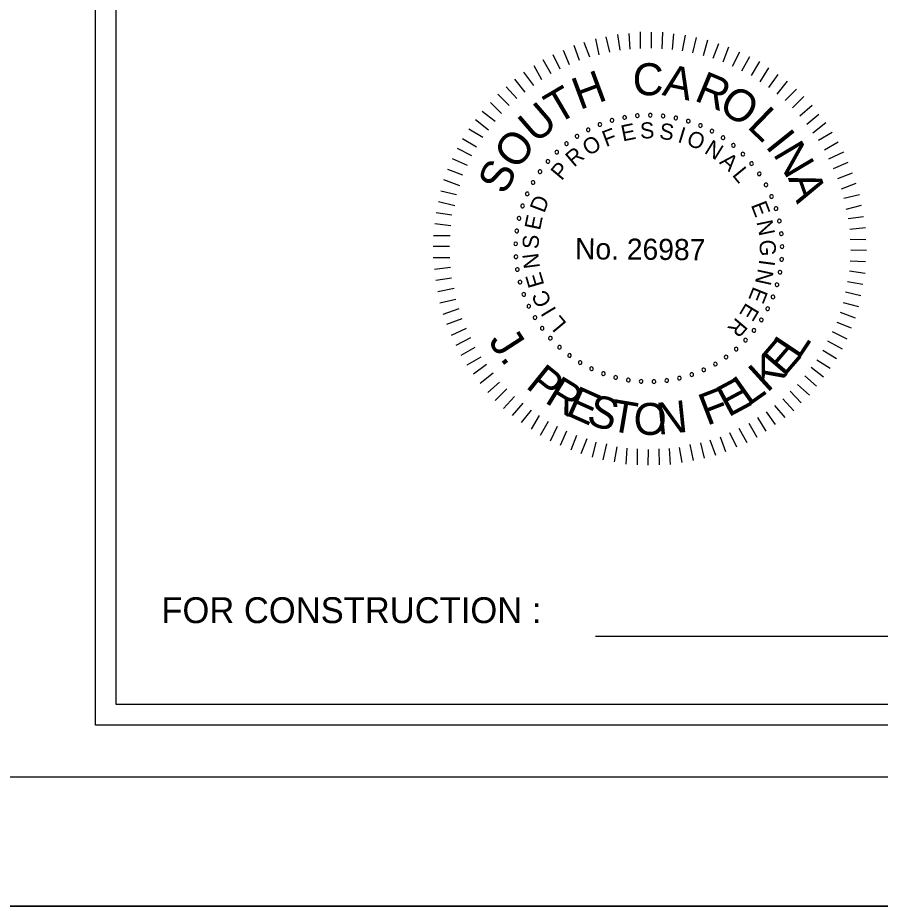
# Model space of a CAD drawing. Extents: x -1142 to 658, y -589 to 511.
# Drawn here: x 260.1 to 427, y -589.3 to -417.4 of the extents above; entities that cross this region are included whole.
import ezdxf

# ---------------------------------------------------------------- set-up
doc = ezdxf.new("R2010")
doc.units = 0
for name, color, linetype in [('BR_BORDER LINES', 7, 'Continuous'), ('BR_TEXT', 7, 'Continuous'), ('Default', 7, 'Continuous'), ('Level 31', 7, 'Continuous'), ('RD_SHT_IplotShp', 7, 'Continuous')]:
    doc.layers.add(name, color=color, linetype=linetype)

msp = doc.modelspace()

# ---------------------------------------------------------------- linework, layer by layer
at = {"layer": 'BR_BORDER LINES'}
msp.add_line((-1041.79, -564.26), (633.21, -564.26), dxfattribs=at)
at = {"layer": 'BR_TEXT'}
for p, q in [((374.63, -424.04), (373.93, -421.08)), ((376.61, -423.67), (376.16, -420.62)), ((378.58, -423.47), (378.4, -420.43)), ((380.56, -423.36), (380.59, -420.14)), ((382.66, -423.25), (382.69, -420.16)), ((384.76, -423.4), (384.88, -420.18)), ((386.78, -423.54), (387.02, -420.5)), ((388.71, -423.77), (389.25, -420.73)), ((390.72, -424.18), (391.43, -421.22)), ((368.78, -425.67), (367.74, -422.74)), ((370.76, -425.04), (369.67, -422.16)), ((372.57, -424.54), (371.91, -421.49)), ((392.78, -424.71), (393.58, -421.67)), ((394.62, -425.24), (395.71, -422.37)), ((364.99, -427.35), (363.69, -424.55)), ((366.85, -426.51), (365.67, -423.71)), ((396.59, -425.9), (397.68, -422.99)), ((398.38, -426.77), (399.78, -423.99)), ((363.27, -428.24), (361.75, -425.52)), ((400.18, -427.64), (401.74, -424.87)), ((402.06, -428.56), (403.67, -425.87)), ((359.95, -430.49), (357.99, -427.94)), ((361.5, -429.43), (359.98, -426.71)), ((403.72, -429.77), (405.42, -427.09)), ((358.26, -431.76), (356.27, -429.25)), ((405.39, -430.86), (407.21, -428.35)), ((407.01, -432.16), (409.04, -429.69)), ((356.62, -432.99), (354.54, -430.74)), ((408.58, -433.42), (410.74, -431.21)), ((355.15, -434.35), (352.94, -432.15)), ((409.99, -434.8), (412.15, -432.63)), ((353.68, -435.89), (351.51, -433.76)), ((411.39, -436.36), (413.77, -434.28)), ((352.42, -437.46), (349.95, -435.51)), ((412.75, -437.96), (415.08, -436.05)), ((351.12, -439.12), (348.65, -437.13)), ((413.94, -439.64), (416.4, -437.69)), ((350.04, -440.57), (347.35, -438.92)), ((415.04, -441.11), (417.67, -439.5)), ((348.82, -442.41), (346.13, -440.8)), ((416.14, -442.97), (418.81, -441.4)), ((347.95, -444.12), (345.13, -442.72)), ((417.03, -444.69), (419.91, -443.34)), ((347.07, -445.96), (344.21, -444.69)), ((346.2, -447.88), (343.29, -446.78)), ((417.91, -446.54), (420.76, -445.32)), ((418.76, -448.48), (421.6, -447.43)), ((345.58, -449.89), (342.5, -448.75)), ((419.43, -450.5), (422.31, -449.41)), ((344.97, -451.69), (341.93, -450.93)), ((419.93, -452.31), (422.94, -451.6)), ((344.61, -453.79), (341.48, -452.99)), ((420.34, -454.41), (423.35, -453.67)), ((344.08, -455.59), (341.03, -455.17)), ((343.85, -457.64), (340.76, -457.28)), ((420.75, -456.22), (423.72, -455.86)), ((421.08, -458.28), (424.13, -457.96)), ((343.7, -459.62), (340.48, -459.59)), ((421.15, -460.26), (424.15, -460.28)), ((343.6, -461.67), (340.47, -461.65)), ((421.26, -462.32), (424.3, -462.34)), ((343.67, -463.82), (340.45, -463.88)), ((343.78, -465.75), (340.69, -466.11)), ((421.11, -464.46), (424.12, -464.57)), ((421.01, -466.39), (424.05, -466.8)), ((343.98, -467.81), (340.93, -468.26)), ((420.65, -468.45), (423.61, -468.94)), ((344.48, -469.79), (341.34, -470.45)), ((420.21, -470.42), (423.2, -471.13)), ((344.8, -471.9), (341.75, -472.6)), ((419.76, -472.52), (422.76, -473.27)), ((345.39, -473.75), (342.29, -474.79)), ((419.23, -474.36), (422.1, -475.45)), ((345.97, -475.68), (343.05, -476.73)), ((346.81, -477.54), (343.93, -478.88)), ((418.53, -476.28), (421.35, -477.38)), ((347.66, -479.34), (344.81, -480.82)), ((417.65, -478.12), (420.47, -479.52)), ((348.5, -481.2), (345.79, -482.76)), ((416.74, -479.92), (419.6, -481.44)), ((349.69, -483.05), (346.97, -484.62)), ((415.82, -481.75), (418.47, -483.36)), ((350.75, -484.52), (348.24, -486.34)), ((414.69, -483.59), (417.29, -485.2)), ((352.02, -486.2), (349.52, -488.16)), ((413.56, -485.04), (415.99, -486.9)), ((353.25, -487.89), (351.05, -489.93)), ((412.35, -486.7), (414.65, -488.69)), ((354.7, -489.19), (352.45, -491.44)), ((409.53, -489.64), (411.66, -491.93)), ((410.96, -488.36), (413.3, -490.44)), ((356.15, -490.7), (354.02, -493)), ((408.11, -491.13), (410.23, -493.46)), ((357.77, -492), (355.73, -494.34)), ((359.43, -493.3), (357.44, -495.69)), ((406.51, -492.4), (408.5, -494.78)), ((360.96, -494.39), (359.4, -496.99)), ((403.18, -494.74), (404.84, -497.37)), ((404.87, -493.68), (406.65, -496.09)), ((362.71, -495.52), (361.15, -498.21)), ((364.42, -496.52), (363.07, -499.3)), ((399.61, -496.81), (401.13, -499.61)), ((401.5, -495.84), (403.07, -498.55)), ((366.26, -497.39), (365.04, -500.17)), ((368.18, -498.26), (367.09, -501.09)), ((395.99, -498.49), (397.04, -501.34)), ((397.8, -497.65), (399.15, -500.45)), ((370.15, -498.88), (369.01, -501.79)), ((371.95, -499.5), (371.24, -502.45)), ((374.01, -499.86), (373.25, -502.94)), ((390.1, -499.99), (390.76, -503.09)), ((392.16, -499.67), (392.91, -502.63)), ((394.01, -499.08), (395.06, -502.01)), ((375.97, -500.43), (375.48, -503.35)), ((377.95, -500.66), (377.71, -503.75)), ((379.92, -500.81), (379.9, -503.9)), ((382.02, -500.95), (382, -504)), ((384.13, -500.84), (384.19, -503.93)), ((386.14, -500.73), (386.33, -503.82)), ((388.07, -500.53), (388.57, -503.45))]:
    msp.add_line(p, q, dxfattribs=at)
for centre, start, end in [((377.49, -436.68), 10.6038, 190.6038), ((377.49, -436.68), 190.6038, 10.6038), ((379.96, -436.34), 5.0653, 185.0653), ((379.96, -436.34), 185.0653, 5.0653), ((382.45, -436.25), 359.5268, 179.5268), ((382.45, -436.25), 179.5268, 359.5268), ((384.94, -436.39), 353.9884, 173.9884), ((384.94, -436.39), 173.9884, 353.9884), ((387.4, -436.78), 348.4499, 168.4499), ((387.4, -436.78), 168.4499, 348.4499), ((372.71, -438.05), 21.6807, 201.6807), ((372.71, -438.05), 201.6807, 21.6807), ((375.06, -437.25), 16.1422, 196.1422), ((375.06, -437.25), 196.1422, 16.1422), ((389.81, -437.4), 162.9114, 342.9114), ((389.81, -437.4), 342.9114, 162.9114), ((392.15, -438.25), 157.373, 337.373), ((392.15, -438.25), 337.373, 157.373), ((368.28, -440.32), 32.7576, 212.7576), ((368.28, -440.32), 212.7576, 32.7576), ((370.44, -439.08), 27.2191, 207.2191), ((370.44, -439.08), 207.2191, 27.2191), ((394.4, -439.32), 151.8345, 331.8345), ((394.4, -439.32), 331.8345, 151.8345), ((366.24, -441.76), 38.2961, 218.2961), ((366.24, -441.76), 218.2961, 38.2961), ((396.54, -440.61), 146.2961, 326.2961), ((396.54, -440.61), 326.2961, 146.2961), ((398.54, -442.09), 140.7576, 320.7576), ((398.54, -442.09), 320.7576, 140.7576), ((364.36, -443.4), 43.8345, 223.8345), ((364.36, -443.4), 223.8345, 43.8345), ((400.38, -443.77), 135.2191, 315.2191), ((400.38, -443.77), 315.2191, 135.2191), ((362.65, -445.2), 49.373, 229.373), ((362.65, -445.2), 229.373, 49.373), ((402.06, -445.61), 309.6807, 129.6807), ((361.11, -447.17), 54.9114, 234.9114), ((361.11, -447.17), 234.9114, 54.9114), ((402.06, -445.61), 129.6807, 309.6807), ((403.55, -447.6), 124.1422, 304.1422), ((403.55, -447.6), 304.1422, 124.1422), ((359.78, -449.27), 60.4499, 240.4499), ((359.78, -449.27), 240.4499, 60.4499), ((404.85, -449.73), 118.6038, 298.6038), ((404.85, -449.73), 298.6038, 118.6038), ((358.65, -451.49), 65.9884, 245.9884), ((358.65, -451.49), 245.9884, 65.9884), ((405.93, -451.98), 113.0653, 293.0653), ((405.93, -451.98), 293.0653, 113.0653), ((357.74, -453.81), 71.5268, 251.5268), ((357.74, -453.81), 251.5268, 71.5268), ((406.79, -454.31), 107.5268, 287.5268), ((406.79, -454.31), 287.5268, 107.5268), ((357.07, -456.21), 77.0653, 257.0653), ((357.07, -456.21), 257.0653, 77.0653), ((407.42, -456.73), 101.9884, 281.9884), ((407.42, -456.73), 281.9884, 101.9884), ((356.62, -458.66), 82.6038, 262.6038), ((356.62, -458.66), 262.6038, 82.6038), ((407.81, -459.19), 96.4499, 276.4499), ((407.81, -459.19), 276.4499, 96.4499), ((356.41, -461.14), 88.1422, 268.1422), ((356.41, -461.14), 268.1422, 88.1422), ((407.97, -461.67), 90.9114, 270.9114), ((407.97, -461.67), 270.9114, 90.9114), ((356.45, -463.64), 93.6807, 273.6807), ((356.45, -463.64), 273.6807, 93.6807), ((407.88, -464.16), 85.373, 265.373), ((407.88, -464.16), 265.373, 85.373), ((356.72, -466.11), 99.2191, 279.2191), ((356.72, -466.11), 279.2191, 99.2191), ((407.56, -466.63), 79.8345, 259.8345), ((407.56, -466.63), 259.8345, 79.8345), ((357.24, -468.55), 104.7576, 284.7576), ((357.24, -468.55), 284.7576, 104.7576), ((406.99, -469.06), 74.2961, 254.2961), ((406.99, -469.06), 254.2961, 74.2961), ((357.98, -470.93), 110.2961, 290.2961), ((357.98, -470.93), 290.2961, 110.2961), ((406.2, -471.42), 68.7576, 248.7576), ((406.2, -471.42), 248.7576, 68.7576), ((358.95, -473.22), 115.8345, 295.8345), ((358.95, -473.22), 295.8345, 115.8345), ((405.18, -473.7), 63.2191, 243.2191), ((405.18, -473.7), 243.2191, 63.2191), ((360.14, -475.41), 121.373, 301.373), ((360.14, -475.41), 301.373, 121.373), ((403.95, -475.86), 57.6807, 237.6807), ((403.95, -475.86), 237.6807, 57.6807), ((361.54, -477.48), 126.9114, 306.9114), ((361.54, -477.48), 306.9114, 126.9114), ((402.51, -477.9), 52.1422, 232.1422), ((402.51, -477.9), 232.1422, 52.1422), ((363.12, -479.4), 132.4499, 312.4499), ((363.12, -479.4), 312.4499, 132.4499), ((400.89, -479.78), 46.6038, 226.6038), ((400.89, -479.78), 226.6038, 46.6038), ((364.89, -481.16), 137.9884, 317.9884), ((364.89, -481.16), 317.9884, 137.9884), ((399.08, -481.51), 41.0653, 221.0653), ((399.08, -481.51), 221.0653, 41.0653), ((366.82, -482.74), 143.5268, 323.5268), ((366.82, -482.74), 323.5268, 143.5268), ((397.13, -483.05), 35.5268, 215.5268), ((397.13, -483.05), 215.5268, 35.5268), ((368.89, -484.12), 149.0653, 329.0653), ((368.89, -484.12), 329.0653, 149.0653), ((395.03, -484.39), 29.9884, 209.9884), ((395.03, -484.39), 209.9884, 29.9884), ((371.08, -485.3), 154.6038, 334.6038), ((371.08, -485.3), 334.6038, 154.6038), ((373.38, -486.27), 160.1422, 340.1422), ((373.38, -486.27), 340.1422, 160.1422), ((390.49, -486.44), 18.9114, 198.9114), ((390.49, -486.44), 198.9114, 18.9114), ((392.81, -485.53), 24.4499, 204.4499), ((392.81, -485.53), 204.4499, 24.4499), ((375.76, -487), 165.6807, 345.6807), ((375.76, -487), 345.6807, 165.6807), ((378.2, -487.51), 351.2191, 171.2191), ((378.2, -487.51), 171.2191, 351.2191), ((380.67, -487.77), 356.7576, 176.7576), ((380.67, -487.77), 176.7576, 356.7576), ((383.17, -487.8), 2.2961, 182.2961), ((383.17, -487.8), 182.2961, 2.2961), ((385.65, -487.58), 7.8345, 187.8345), ((385.65, -487.58), 187.8345, 7.8345), ((388.1, -487.13), 13.373, 193.373), ((388.1, -487.13), 193.373, 13.373)]:
    msp.add_arc(centre, 0.351, start, end, dxfattribs=at)
at = {"layer": 'Default'}
msp.add_line((371.83, -537.07), (510.46, -537.07), dxfattribs=at)
for points in [[(275.07, -376.26), (593.07, -376.26), (593.07, -554.26), (275.07, -554.26)], [(279.07, -380.26), (589.07, -380.26), (589.07, -550.26), (279.07, -550.26)]]:
    msp.add_lwpolyline(points, close=True, dxfattribs=at)
at = {"layer": 'Level 31'}
msp.add_lwpolyline([(-1141.79, 510.67), (-1141.79, -589.33), (658.21, -589.33), (658.21, 510.67)], dxfattribs=at)
at = {"layer": 'RD_SHT_IplotShp'}
msp.add_line((-1141.79, -589.26), (658.21, -589.26), dxfattribs=at)

# ---------------------------------------------------------------- texts
at = {"layer": 'BR_TEXT'}
for s, height, rotation, p in [('C', 6.2, 359.5482, (379.02, -432.37)), ('H', 6.2, 20.3637, (368.8, -435.28)), ('A', 6.2, 348.1981, (384.6, -432.33)), ('R', 6.2, 337.4344, (390.76, -433.32)), ('T', 6.2, 30.4992, (364.41, -438.16)), ('O', 6.2, 326.5869, (395.37, -435.16)), ('U', 6.2, 40.8022, (360.35, -441.9)), ('L', 6.2, 315.9488, (401, -438.55)), ('E', 3.11, 11.4103, (377.13, -441.34)), ('S', 3.11, 2.208, (380.52, -440.79)), ('S', 3.11, 352.6608, (384.08, -440.8)), ('O', 6.2, 52.0267, (356.62, -447.09)), ('F', 3.11, 20.6127, (373.87, -442.43)), ('I', 3.11, 343.1136, (387.59, -441.41)), ('O', 3.11, 338.4392, (389.26, -441.91)), ('I', 6.2, 308.6613, (404.57, -442.26)), ('O', 3.11, 30.8477, (370.5, -444.23)), ('N', 3.11, 328.2042, (392.74, -443.48)), ('N', 6.2, 300.7037, (406.1, -443.73)), ('R', 3.11, 40.3949, (367.69, -446.42)), ('S', 6.2, 63.2511, (354.35, -451.87)), ('A', 3.11, 318.657, (395.69, -445.48)), ('P', 3.11, 49.9421, (365.29, -449.05)), ('L', 3.11, 309.4546, (398.18, -447.85)), ('A', 6.2, 289.4792, (409.06, -448.38)), ('D', 3.11, 69.0364, (361.94, -455.32)), ('E', 3.11, 291.049, (401.88, -453.62)), ('E', 3.11, 78.2388, (361.11, -458.65)), ('N', 3.11, 281.8466, (402.99, -456.87)), ('S', 3.11, 87.786, (360.83, -462.2)), ('No. 26987', 4.087, 359.5268, (367.88, -464.12)), ('G', 3.11, 272.2995, (403.57, -460.38)), ('N', 3.11, 97.3332, (361.13, -465.75)), ('I', 3.11, 262.4084, (403.56, -464.07)), ('E', 3.11, 106.5355, (361.98, -469.08)), ('N', 3.11, 257.7339, (403.33, -465.8)), ('C', 3.11, 116.4266, (363.48, -472.46)), ('E', 3.11, 248.1867, (402.43, -469.25)), ('E', 3.11, 238.9844, (401.03, -472.39)), ('I', 3.11, 121.1011, (364.38, -473.95)), ('L', 3.11, 129.9595, (366.41, -476.56)), ('R', 3.11, 229.782, (399.15, -475.26)), ('J', 6.18, 302.9559, (351.02, -479.98)), ('E', 6.18, 49.3639, (408.32, -487.07)), ('L', 6.18, 56.4247, (411.19, -483.69)), ('K', 6.18, 42.3031, (405.05, -490.08)), ('.', 6.18, 309.3974, (353.22, -483.38)), ('P', 6.18, 321.1035, (358.15, -488.84)), ('R', 6.18, 328.5359, (361.81, -491.74)), ('E', 6.18, 28.1814, (397.54, -494.78)), ('L', 6.18, 35.2422, (401.44, -492.66)), ('E', 6.18, 335.9684, (365.82, -494.15)), ('F', 6.18, 21.1206, (393.4, -496.4)), ('S', 6.18, 343.0292, (369.88, -495.93)), ('T', 6.18, 350.4617, (374.36, -497.26)), ('N', 6.18, 5.8221, (383.96, -498.11)), ('O', 6.18, 358.1419, (379.13, -498.01))]:
    msp.add_text(s, height=height, rotation=rotation, dxfattribs=at).set_placement(p)
at = {"layer": 'Default'}
msp.add_text('FOR CONSTRUCTION :', height=5.0001, dxfattribs=at).set_placement((287.84, -534.54))

doc.saveas('drawing.dxf')
